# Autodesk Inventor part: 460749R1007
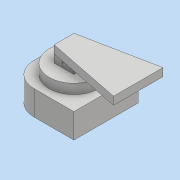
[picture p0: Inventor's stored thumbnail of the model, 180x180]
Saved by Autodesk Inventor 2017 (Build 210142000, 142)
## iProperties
Created: 2016-07
Part Number: 460749R1007
Material: Generic
Document SubType Name: Modeling
Designer: Polytech
Density: 1 g/cm^3
Appearance: Default
Author: Polytech
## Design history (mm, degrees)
sketch "Sketch1"
  geometry: C1 r 23 at (0, 0); 1 further point
  constraints: 1 centre point, 1 coincident
  dimensions: "d0" = 46 diameter of C1
extrude "Extrusion1" new body sketch "Sketch1" distance "d1" = 18; taper "d2" = 0 deg
sketch "Sketch2"
  geometry: L1 (-11.75, 48.75)-(48.75, 48.75); L2 (48.75, 48.75)-(48.75, -48.75); L3 (48.75, -48.75)-(-11.75, -48.75); L4 (-48.75, -11.75)-(-48.75, 11.75); L5 (-48.75, 48.75)-(48.75, -48.75); L6 (48.75, 48.75)-(-48.75, -48.75); A1 r 37 centre (-11.75, 11.75) between (-11.75, 48.75) and (-48.75, 11.75); A2 r 37 centre (-11.75, -11.75) between (-48.75, -11.75) and (-11.75, -48.75); 1 further point
  constraints: 12 end point, 4 point on circle, 4 point on line, 4 tangent, 2 centre point, 2 midpoint, 2 parallel, 1 equal radius, 1 horizontal, 1 perpendicular
  dimensions: "d3" = 97.5 distance of L5.start L1.end; "d4" = 97.5 distance of L6.end L5.start; "d5" = 37 radius of A1
extrude "Extrusion2" join sketch "Sketch2" distance "d6" = 37.5; taper "d7" = 0 deg
sketch "Sketch3"
  geometry: C1 r 37.5 at (0, 0); 1 further point
  constraints: 1 centre point, 1 coincident
  dimensions: "d8" = 75 diameter of C1
extrude "Extrusion3" join sketch "Sketch3" distance "d9" = 15; taper "d10" = 0 deg
sketch "Sketch4"
  geometry: L1 (-15, 15)-(15, 15); L2 (15, 15)-(15, -15); L3 (15, -15)-(-15, -15); L4 (-15, -15)-(-15, 15); L5 (-15, 15)-(15, -15); L6 (15, 15)-(-15, -15); 1 further point
  constraints: 12 end point, 2 midpoint, 2 parallel, 1 horizontal, 1 perpendicular
  dimensions: "d11" = 30 distance of L2.end L3.end; "d12" = 30 distance of L1.end L2.end
extrude "Extrusion4" join sketch "Sketch4" distance "d13" = 12; taper "d14" = 0 deg
sketch "Sketch5"
  geometry: L1 (-15, 6)-(15, 6); L2 (15, 6)-(15, -6); L3 (15, -6)-(-15, -6); L4 (-15, -6)-(-15, 6); L5 (-15, 6)-(15, -6); L6 (15, 6)-(-15, -6); 1 further point
  constraints: 12 end point, 2 midpoint, 2 parallel, 1 horizontal, 1 perpendicular
  dimensions: "d15" = 30 distance of L2.end L3.end; "d16" = 12 distance of L1.end L2.end
extrude "Extrusion5" cut sketch "Sketch5" distance "d17" = 12; taper "d18" = 0 deg
sketch "Sketch6"
  geometry: L1 (52.5, 0)-(-22.5, 0) reference; C1 r 3 at (15, 6); 1 further point
  constraints: 1 centre point, 1 vertical alignment
  dimensions: "d19" = 3 radius of C1; "d20" = 6 distance from line of L1 C1.centre
extrude "Extrusion6" cut sketch "Sketch6" stored distance "d21" = 12; taper "d22" = 0 deg
sketch "Sketch7"
  geometry: L1 (-15, 15)-(-15, -15); L2 (-15, -15)-(97.5, -37.5); L3 (97.5, -37.5)-(97.5, 37.5); L4 (97.5, 37.5)-(-15, 15); 4 further points
  constraints: 8 end point, 2 coincident, 1 horizontal alignment, 1 midpoint, 1 parallel, 1 vertical
  dimensions: "d23" = 75 distance of L2.end L3.end; "d24" = 97.5 distance from line of L3 point (0, 0)
extrude "Extrusion7" join sketch "Sketch7" distance "d25" = 12; taper "d26" = 0 deg
sketch "Sketch8"
  geometry: C1 r 23 at (0, 0); 1 further point
  constraints: 1 centre point, 1 coincident
  dimensions: "d27" = 46 diameter of C1
extrude "Extrusion8" cut sketch "Sketch8" distance "d28" = 24.5; taper "d29" = 0 deg
body "Solid1"
